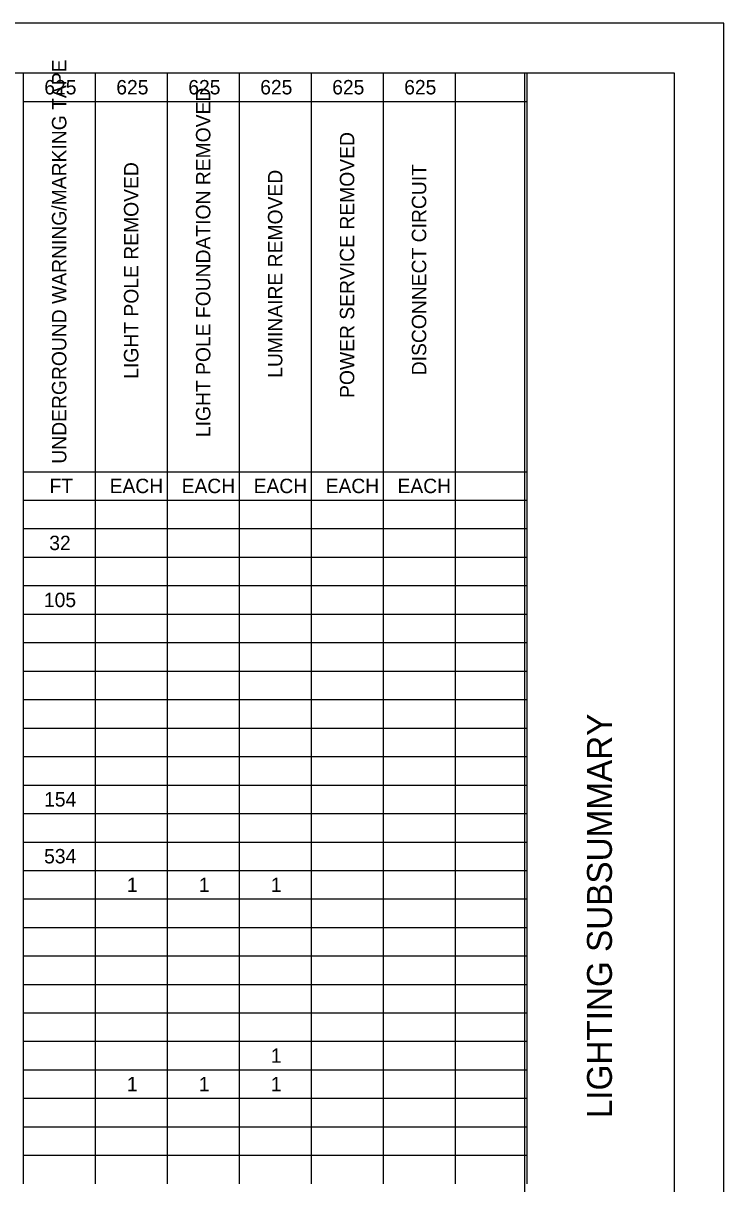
# Model space of a CAD drawing. Extents: x 0 to 34, y 0 to 22.
# Drawn here: x 26.95 to 34, y 10.33 to 22 of the extents above; entities that cross this region are included whole.
import ezdxf

# ---------------------------------------------------------------- set-up
doc = ezdxf.new("R2010")
doc.units = 0
for name, color, linetype in [('Default', 7, 'Continuous'), ('SH_Border', 7, 'Continuous'), ('SH_Cut_Line', 7, 'Continuous'), ('SH_Data', 7, 'Continuous')]:
    doc.layers.add(name, color=color, linetype=linetype)

msp = doc.modelspace()

# ---------------------------------------------------------------- linework, layer by layer
at = {"layer": 'Default'}
for p, q in [((26.955, 21.5), (27.679, 21.5)), ((26.955, 21.5), (26.955, 21.214)), ((27.679, 21.5), (29.85, 21.5)), ((27.679, 21.5), (27.679, 21.214)), ((28.402, 21.5), (28.402, 21.214)), ((29.126, 21.5), (29.126, 21.214)), ((29.85, 21.5), (30.574, 21.5)), ((29.85, 21.5), (29.85, 21.214)), ((30.574, 21.5), (31.297, 21.5)), ((30.574, 21.5), (30.574, 21.214)), ((31.297, 21.5), (32.021, 21.5)), ((31.297, 21.5), (31.297, 21.214)), ((32.021, 21.5), (32.021, 21.214)), ((26.955, 21.214), (27.679, 21.214)), ((26.955, 21.214), (26.955, 20.927)), ((27.679, 21.214), (29.85, 21.214)), ((27.679, 21.214), (27.679, 20.927)), ((28.402, 21.214), (28.402, 20.927)), ((29.126, 21.214), (29.126, 20.927)), ((29.85, 21.214), (30.574, 21.214)), ((29.85, 21.214), (29.85, 20.927)), ((30.574, 21.214), (31.297, 21.214)), ((30.574, 21.214), (30.574, 20.927)), ((31.297, 21.214), (32.021, 21.214)), ((31.297, 21.214), (31.297, 20.927)), ((32.021, 21.214), (32.021, 20.927)), ((26.955, 20.927), (26.955, 20.641)), ((27.679, 20.927), (27.679, 20.641)), ((28.402, 20.927), (28.402, 20.641)), ((29.126, 20.927), (29.126, 20.641)), ((29.85, 20.927), (29.85, 20.641)), ((30.574, 20.927), (30.574, 20.641)), ((31.297, 20.927), (31.297, 20.641)), ((32.021, 20.927), (32.021, 20.641)), ((26.955, 20.641), (26.955, 20.354)), ((27.679, 20.641), (27.679, 20.354)), ((28.402, 20.641), (28.402, 20.354)), ((29.126, 20.641), (29.126, 20.354)), ((29.85, 20.641), (29.85, 20.354)), ((30.574, 20.641), (30.574, 20.354)), ((31.297, 20.641), (31.297, 20.354)), ((32.021, 20.641), (32.021, 20.354)), ((26.955, 20.354), (26.955, 20.068)), ((27.679, 20.354), (27.679, 20.068)), ((28.402, 20.354), (28.402, 20.068)), ((29.126, 20.354), (29.126, 20.068)), ((29.85, 20.354), (29.85, 20.068)), ((30.574, 20.354), (30.574, 20.068)), ((31.297, 20.354), (31.297, 20.068)), ((32.021, 20.354), (32.021, 20.068)), ((26.955, 20.068), (26.955, 19.782)), ((27.679, 20.068), (27.679, 19.782)), ((28.402, 20.068), (28.402, 19.782)), ((29.126, 20.068), (29.126, 19.782)), ((29.85, 20.068), (29.85, 19.782)), ((30.574, 20.068), (30.574, 19.782)), ((31.297, 20.068), (31.297, 19.782)), ((32.021, 20.068), (32.021, 19.782)), ((26.955, 19.782), (26.955, 19.495)), ((27.679, 19.782), (27.679, 19.495)), ((28.402, 19.782), (28.402, 19.495)), ((29.126, 19.782), (29.126, 19.495)), ((29.85, 19.782), (29.85, 19.495)), ((30.574, 19.782), (30.574, 19.495)), ((31.297, 19.782), (31.297, 19.495)), ((32.021, 19.782), (32.021, 19.495)), ((26.955, 19.495), (26.955, 19.209)), ((27.679, 19.495), (27.679, 19.209)), ((28.402, 19.495), (28.402, 19.209)), ((29.126, 19.495), (29.126, 19.209)), ((29.85, 19.495), (29.85, 19.209)), ((30.574, 19.495), (30.574, 19.209)), ((31.297, 19.495), (31.297, 19.209)), ((32.021, 19.495), (32.021, 19.209)), ((26.955, 19.209), (26.955, 18.922)), ((27.679, 19.209), (27.679, 18.922)), ((28.402, 19.209), (28.402, 18.922)), ((29.126, 19.209), (29.126, 18.922)), ((29.85, 19.209), (29.85, 18.922)), ((30.574, 19.209), (30.574, 18.922)), ((31.297, 19.209), (31.297, 18.922)), ((32.021, 19.209), (32.021, 18.922)), ((26.955, 18.922), (26.955, 18.636)), ((27.679, 18.922), (27.679, 18.636)), ((28.402, 18.922), (28.402, 18.636)), ((29.126, 18.922), (29.126, 18.636)), ((29.85, 18.922), (29.85, 18.636)), ((30.574, 18.922), (30.574, 18.636)), ((31.297, 18.922), (31.297, 18.636)), ((32.021, 18.922), (32.021, 18.636)), ((26.955, 18.636), (26.955, 18.35)), ((27.679, 18.636), (27.679, 18.35)), ((28.402, 18.636), (28.402, 18.35)), ((29.126, 18.636), (29.126, 18.35)), ((29.85, 18.636), (29.85, 18.35)), ((30.574, 18.636), (30.574, 18.35)), ((31.297, 18.636), (31.297, 18.35)), ((32.021, 18.636), (32.021, 18.35)), ((26.955, 18.35), (26.955, 18.063)), ((27.679, 18.35), (27.679, 18.063)), ((28.402, 18.35), (28.402, 18.063)), ((29.126, 18.35), (29.126, 18.063)), ((29.85, 18.35), (29.85, 18.063)), ((30.574, 18.35), (30.574, 18.063)), ((31.297, 18.35), (31.297, 18.063)), ((32.021, 18.35), (32.021, 18.063)), ((26.955, 18.063), (26.955, 17.777)), ((27.679, 18.063), (27.679, 17.777)), ((28.402, 18.063), (28.402, 17.777)), ((29.126, 18.063), (29.126, 17.777)), ((29.85, 18.063), (29.85, 17.777)), ((30.574, 18.063), (30.574, 17.777)), ((31.297, 18.063), (31.297, 17.777)), ((32.021, 18.063), (32.021, 17.777)), ((26.955, 17.777), (26.955, 17.49)), ((27.679, 17.777), (27.679, 17.49)), ((28.402, 17.777), (28.402, 17.49)), ((29.126, 17.777), (29.126, 17.49)), ((29.85, 17.777), (29.85, 17.49)), ((30.574, 17.777), (30.574, 17.49)), ((31.297, 17.777), (31.297, 17.49)), ((32.021, 17.777), (32.021, 17.49)), ((26.955, 17.49), (27.679, 17.49)), ((26.955, 17.49), (26.955, 17.204)), ((27.679, 17.49), (29.85, 17.49)), ((27.679, 17.49), (27.679, 17.204)), ((28.402, 17.49), (28.402, 17.204)), ((29.126, 17.49), (29.126, 17.204)), ((29.85, 17.49), (30.574, 17.49)), ((29.85, 17.49), (29.85, 17.204)), ((30.574, 17.49), (31.297, 17.49)), ((30.574, 17.49), (30.574, 17.204)), ((31.297, 17.49), (32.021, 17.49)), ((31.297, 17.49), (31.297, 17.204)), ((32.021, 17.49), (32.021, 17.204)), ((26.955, 17.204), (27.679, 17.204)), ((26.955, 17.204), (26.955, 16.918)), ((27.679, 17.204), (29.85, 17.204)), ((27.679, 17.204), (27.679, 16.918)), ((28.402, 17.204), (28.402, 16.918)), ((29.126, 17.204), (29.126, 16.918)), ((29.85, 17.204), (30.574, 17.204)), ((29.85, 17.204), (29.85, 16.918)), ((30.574, 17.204), (31.297, 17.204)), ((30.574, 17.204), (30.574, 16.918)), ((31.297, 17.204), (32.021, 17.204)), ((31.297, 17.204), (31.297, 16.918)), ((32.021, 17.204), (32.021, 16.918)), ((26.955, 16.918), (27.679, 16.918)), ((26.955, 16.918), (26.955, 16.631)), ((27.679, 16.918), (29.85, 16.918)), ((27.679, 16.918), (27.679, 16.631)), ((28.402, 16.918), (28.402, 16.631)), ((29.126, 16.918), (29.126, 16.631)), ((29.85, 16.918), (30.574, 16.918)), ((29.85, 16.918), (29.85, 16.631)), ((30.574, 16.918), (31.297, 16.918)), ((30.574, 16.918), (30.574, 16.631)), ((31.297, 16.918), (32.021, 16.918)), ((31.297, 16.918), (31.297, 16.631)), ((32.021, 16.918), (32.021, 16.631)), ((26.955, 16.631), (27.679, 16.631)), ((26.955, 16.631), (26.955, 16.345)), ((27.679, 16.631), (29.85, 16.631)), ((27.679, 16.631), (27.679, 16.345)), ((28.402, 16.631), (28.402, 16.345)), ((29.126, 16.631), (29.126, 16.345)), ((29.85, 16.631), (30.574, 16.631)), ((29.85, 16.631), (29.85, 16.345)), ((30.574, 16.631), (31.297, 16.631)), ((30.574, 16.631), (30.574, 16.345)), ((31.297, 16.631), (32.021, 16.631)), ((31.297, 16.631), (31.297, 16.345)), ((32.021, 16.631), (32.021, 16.345)), ((26.955, 16.345), (27.679, 16.345)), ((26.955, 16.345), (26.955, 16.058)), ((27.679, 16.345), (29.85, 16.345)), ((27.679, 16.345), (27.679, 16.058)), ((28.402, 16.345), (28.402, 16.058)), ((29.126, 16.345), (29.126, 16.058)), ((29.85, 16.345), (30.574, 16.345)), ((29.85, 16.345), (29.85, 16.058)), ((30.574, 16.345), (31.297, 16.345)), ((30.574, 16.345), (30.574, 16.058)), ((31.297, 16.345), (32.021, 16.345)), ((31.297, 16.345), (31.297, 16.058)), ((32.021, 16.345), (32.021, 16.058)), ((26.955, 16.058), (27.679, 16.058)), ((26.955, 16.058), (26.955, 15.772)), ((27.679, 16.058), (29.85, 16.058)), ((27.679, 16.058), (27.679, 15.772)), ((28.402, 16.058), (28.402, 15.772)), ((29.126, 16.058), (29.126, 15.772)), ((29.85, 16.058), (30.574, 16.058)), ((29.85, 16.058), (29.85, 15.772)), ((30.574, 16.058), (31.297, 16.058)), ((30.574, 16.058), (30.574, 15.772)), ((31.297, 16.058), (32.021, 16.058)), ((31.297, 16.058), (31.297, 15.772)), ((32.021, 16.058), (32.021, 15.772)), ((26.955, 15.772), (27.679, 15.772)), ((26.955, 15.772), (26.955, 15.486)), ((27.679, 15.772), (29.85, 15.772)), ((27.679, 15.772), (27.679, 15.486)), ((28.402, 15.772), (28.402, 15.486)), ((29.126, 15.772), (29.126, 15.486)), ((29.85, 15.772), (30.574, 15.772)), ((29.85, 15.772), (29.85, 15.486)), ((30.574, 15.772), (31.297, 15.772)), ((30.574, 15.772), (30.574, 15.486)), ((31.297, 15.772), (32.021, 15.772)), ((31.297, 15.772), (31.297, 15.486)), ((32.021, 15.772), (32.021, 15.486)), ((26.955, 15.486), (27.679, 15.486)), ((26.955, 15.486), (26.955, 15.199)), ((27.679, 15.486), (29.85, 15.486)), ((27.679, 15.486), (27.679, 15.199)), ((28.402, 15.486), (28.402, 15.199)), ((29.126, 15.486), (29.126, 15.199)), ((29.85, 15.486), (30.574, 15.486)), ((29.85, 15.486), (29.85, 15.199)), ((30.574, 15.486), (31.297, 15.486)), ((30.574, 15.486), (30.574, 15.199)), ((31.297, 15.486), (32.021, 15.486)), ((31.297, 15.486), (31.297, 15.199)), ((32.021, 15.486), (32.021, 15.199)), ((26.955, 15.199), (27.679, 15.199)), ((26.955, 15.199), (26.955, 14.913)), ((27.679, 15.199), (29.85, 15.199)), ((27.679, 15.199), (27.679, 14.913)), ((28.402, 15.199), (28.402, 14.913)), ((29.126, 15.199), (29.126, 14.913)), ((29.85, 15.199), (30.574, 15.199)), ((29.85, 15.199), (29.85, 14.913)), ((30.574, 15.199), (31.297, 15.199)), ((30.574, 15.199), (30.574, 14.913)), ((31.297, 15.199), (32.021, 15.199)), ((31.297, 15.199), (31.297, 14.913)), ((32.021, 15.199), (32.021, 14.913)), ((26.955, 14.913), (27.679, 14.913)), ((26.955, 14.913), (26.955, 14.626)), ((27.679, 14.913), (29.85, 14.913)), ((27.679, 14.913), (27.679, 14.626)), ((28.402, 14.913), (28.402, 14.626)), ((29.126, 14.913), (29.126, 14.626)), ((29.85, 14.913), (30.574, 14.913)), ((29.85, 14.913), (29.85, 14.626)), ((30.574, 14.913), (31.297, 14.913)), ((30.574, 14.913), (30.574, 14.626)), ((31.297, 14.913), (32.021, 14.913)), ((31.297, 14.913), (31.297, 14.626)), ((32.021, 14.913), (32.021, 14.626)), ((26.955, 14.626), (27.679, 14.626)), ((26.955, 14.626), (26.955, 14.34)), ((27.679, 14.626), (29.85, 14.626)), ((27.679, 14.626), (27.679, 14.34)), ((28.402, 14.626), (28.402, 14.34)), ((29.126, 14.626), (29.126, 14.34)), ((29.85, 14.626), (30.574, 14.626)), ((29.85, 14.626), (29.85, 14.34)), ((30.574, 14.626), (31.297, 14.626)), ((30.574, 14.626), (30.574, 14.34)), ((31.297, 14.626), (32.021, 14.626)), ((31.297, 14.626), (31.297, 14.34)), ((32.021, 14.626), (32.021, 14.34)), ((26.955, 14.34), (27.679, 14.34)), ((26.955, 14.34), (26.955, 14.054)), ((27.679, 14.34), (29.85, 14.34)), ((27.679, 14.34), (27.679, 14.054)), ((28.402, 14.34), (28.402, 14.054)), ((29.126, 14.34), (29.126, 14.054)), ((29.85, 14.34), (30.574, 14.34)), ((29.85, 14.34), (29.85, 14.054)), ((30.574, 14.34), (31.297, 14.34)), ((30.574, 14.34), (30.574, 14.054)), ((31.297, 14.34), (32.021, 14.34)), ((31.297, 14.34), (31.297, 14.054)), ((32.021, 14.34), (32.021, 14.054)), ((26.955, 14.054), (27.679, 14.054)), ((26.955, 14.054), (26.955, 13.767)), ((27.679, 14.054), (29.85, 14.054)), ((27.679, 14.054), (27.679, 13.767)), ((28.402, 14.054), (28.402, 13.767)), ((29.126, 14.054), (29.126, 13.767)), ((29.85, 14.054), (30.574, 14.054)), ((29.85, 14.054), (29.85, 13.767)), ((30.574, 14.054), (31.297, 14.054)), ((30.574, 14.054), (30.574, 13.767)), ((31.297, 14.054), (32.021, 14.054)), ((31.297, 14.054), (31.297, 13.767)), ((32.021, 14.054), (32.021, 13.767)), ((26.955, 13.767), (27.679, 13.767)), ((26.955, 13.767), (26.955, 13.481)), ((27.679, 13.767), (29.85, 13.767)), ((27.679, 13.767), (27.679, 13.481)), ((28.402, 13.767), (28.402, 13.481)), ((29.126, 13.767), (29.126, 13.481)), ((29.85, 13.767), (30.574, 13.767)), ((29.85, 13.767), (29.85, 13.481)), ((30.574, 13.767), (31.297, 13.767)), ((30.574, 13.767), (30.574, 13.481)), ((31.297, 13.767), (32.021, 13.767)), ((31.297, 13.767), (31.297, 13.481)), ((32.021, 13.767), (32.021, 13.481)), ((26.955, 13.481), (27.679, 13.481)), ((26.955, 13.481), (26.955, 13.195)), ((27.679, 13.481), (29.85, 13.481)), ((27.679, 13.481), (27.679, 13.195)), ((28.402, 13.481), (28.402, 13.195)), ((29.126, 13.481), (29.126, 13.195)), ((29.85, 13.481), (30.574, 13.481)), ((29.85, 13.481), (29.85, 13.195)), ((30.574, 13.481), (31.297, 13.481)), ((30.574, 13.481), (30.574, 13.195)), ((31.297, 13.481), (32.021, 13.481)), ((31.297, 13.481), (31.297, 13.195)), ((32.021, 13.481), (32.021, 13.195)), ((26.955, 13.195), (27.679, 13.195)), ((26.955, 13.195), (26.955, 12.908)), ((27.679, 13.195), (29.85, 13.195)), ((27.679, 13.195), (27.679, 12.908)), ((28.402, 13.195), (28.402, 12.908)), ((29.126, 13.195), (29.126, 12.908)), ((29.85, 13.195), (30.574, 13.195)), ((29.85, 13.195), (29.85, 12.908)), ((30.574, 13.195), (31.297, 13.195)), ((30.574, 13.195), (30.574, 12.908)), ((31.297, 13.195), (32.021, 13.195)), ((31.297, 13.195), (31.297, 12.908)), ((32.021, 13.195), (32.021, 12.908)), ((26.955, 12.908), (27.679, 12.908)), ((26.955, 12.908), (26.955, 12.622)), ((27.679, 12.908), (29.85, 12.908)), ((27.679, 12.908), (27.679, 12.622)), ((28.402, 12.908), (28.402, 12.622)), ((29.126, 12.908), (29.126, 12.622)), ((29.85, 12.908), (30.574, 12.908)), ((29.85, 12.908), (29.85, 12.622)), ((30.574, 12.908), (31.297, 12.908)), ((30.574, 12.908), (30.574, 12.622)), ((31.297, 12.908), (32.021, 12.908)), ((31.297, 12.908), (31.297, 12.622)), ((32.021, 12.908), (32.021, 12.622)), ((26.955, 12.622), (27.679, 12.622)), ((26.955, 12.622), (26.955, 12.335)), ((27.679, 12.622), (29.85, 12.622)), ((27.679, 12.622), (27.679, 12.335)), ((28.402, 12.622), (28.402, 12.335)), ((29.126, 12.622), (29.126, 12.335)), ((29.85, 12.622), (30.574, 12.622)), ((29.85, 12.622), (29.85, 12.335)), ((30.574, 12.622), (31.297, 12.622)), ((30.574, 12.622), (30.574, 12.335)), ((31.297, 12.622), (32.021, 12.622)), ((31.297, 12.622), (31.297, 12.335)), ((32.021, 12.622), (32.021, 12.335)), ((26.955, 12.335), (27.679, 12.335)), ((26.955, 12.335), (26.955, 12.049)), ((27.679, 12.335), (29.85, 12.335)), ((27.679, 12.335), (27.679, 12.049)), ((28.402, 12.335), (28.402, 12.049)), ((29.126, 12.335), (29.126, 12.049)), ((29.85, 12.335), (30.574, 12.335)), ((29.85, 12.335), (29.85, 12.049)), ((30.574, 12.335), (31.297, 12.335)), ((30.574, 12.335), (30.574, 12.049)), ((31.297, 12.335), (32.021, 12.335)), ((31.297, 12.335), (31.297, 12.049)), ((32.021, 12.335), (32.021, 12.049)), ((26.955, 12.049), (27.679, 12.049)), ((26.955, 12.049), (26.955, 11.763)), ((27.679, 12.049), (29.85, 12.049)), ((27.679, 12.049), (27.679, 11.763)), ((28.402, 12.049), (28.402, 11.763)), ((29.126, 12.049), (29.126, 11.763)), ((29.85, 12.049), (30.574, 12.049)), ((29.85, 12.049), (29.85, 11.763)), ((30.574, 12.049), (31.297, 12.049)), ((30.574, 12.049), (30.574, 11.763)), ((31.297, 12.049), (32.021, 12.049)), ((31.297, 12.049), (31.297, 11.763)), ((32.021, 12.049), (32.021, 11.763)), ((26.955, 11.763), (27.679, 11.763)), ((26.955, 11.763), (26.955, 11.476)), ((27.679, 11.763), (29.85, 11.763)), ((27.679, 11.763), (27.679, 11.476)), ((28.402, 11.763), (28.402, 11.476)), ((29.126, 11.763), (29.126, 11.476)), ((29.85, 11.763), (30.574, 11.763)), ((29.85, 11.763), (29.85, 11.476)), ((30.574, 11.763), (31.297, 11.763)), ((30.574, 11.763), (30.574, 11.476)), ((31.297, 11.763), (32.021, 11.763)), ((31.297, 11.763), (31.297, 11.476)), ((32.021, 11.763), (32.021, 11.476)), ((26.955, 11.476), (27.679, 11.476)), ((26.955, 11.476), (26.955, 11.19)), ((27.679, 11.476), (29.85, 11.476)), ((27.679, 11.476), (27.679, 11.19)), ((28.402, 11.476), (28.402, 11.19)), ((29.126, 11.476), (29.126, 11.19)), ((29.85, 11.476), (30.574, 11.476)), ((29.85, 11.476), (29.85, 11.19)), ((30.574, 11.476), (31.297, 11.476)), ((30.574, 11.476), (30.574, 11.19)), ((31.297, 11.476), (32.021, 11.476)), ((31.297, 11.476), (31.297, 11.19)), ((32.021, 11.476), (32.021, 11.19)), ((26.955, 11.19), (27.679, 11.19)), ((26.955, 11.19), (26.955, 10.903)), ((27.679, 11.19), (29.85, 11.19)), ((27.679, 11.19), (27.679, 10.903)), ((28.402, 11.19), (28.402, 10.903)), ((29.126, 11.19), (29.126, 10.903)), ((29.85, 11.19), (30.574, 11.19)), ((29.85, 11.19), (29.85, 10.903)), ((30.574, 11.19), (31.297, 11.19)), ((30.574, 11.19), (30.574, 10.903)), ((31.297, 11.19), (32.021, 11.19)), ((31.297, 11.19), (31.297, 10.903)), ((32.021, 11.19), (32.021, 10.903)), ((26.955, 10.903), (27.679, 10.903)), ((26.955, 10.903), (26.955, 10.617)), ((27.679, 10.903), (29.85, 10.903)), ((27.679, 10.903), (27.679, 10.617)), ((28.402, 10.903), (28.402, 10.617)), ((29.126, 10.903), (29.126, 10.617)), ((29.85, 10.903), (30.574, 10.903)), ((29.85, 10.903), (29.85, 10.617)), ((30.574, 10.903), (31.297, 10.903)), ((30.574, 10.903), (30.574, 10.617)), ((31.297, 10.903), (32.021, 10.903)), ((31.297, 10.903), (31.297, 10.617)), ((32.021, 10.903), (32.021, 10.617)), ((26.955, 10.617), (27.679, 10.617)), ((26.955, 10.617), (26.955, 10.331)), ((27.679, 10.617), (29.85, 10.617)), ((27.679, 10.617), (27.679, 10.331)), ((28.402, 10.617), (28.402, 10.331)), ((29.126, 10.617), (29.126, 10.331)), ((29.85, 10.617), (30.574, 10.617)), ((29.85, 10.617), (29.85, 10.331)), ((30.574, 10.617), (31.297, 10.617)), ((30.574, 10.617), (30.574, 10.331)), ((31.297, 10.617), (32.021, 10.617)), ((31.297, 10.617), (31.297, 10.331)), ((32.021, 10.617), (32.021, 10.331))]:
    msp.add_line(p, q, dxfattribs=at)
at = {"layer": 'SH_Border'}
msp.add_line((32, 0.5), (32, 21.5), dxfattribs=at)
msp.add_lwpolyline([(1.5, 21.5), (33.5, 21.5), (33.5, 0.5), (1.5, 0.5)], close=True, dxfattribs=at)
at = {"layer": 'SH_Cut_Line'}
msp.add_lwpolyline([(0, 0), (34, 0), (34, 22), (0, 22)], close=True, dxfattribs=at)

# ---------------------------------------------------------------- texts
at = {"layer": 'Default'}
for s, p in [('UNDERGROUND WARNING/MARKING TAPE', (27.389, 17.571)), ('LIGHT POLE FOUNDATION REMOVED', (28.837, 17.838)), ('POWER SERVICE REMOVED', (30.284, 18.232)), ('LIGHT POLE REMOVED', (28.113, 18.425)), ('DISCONNECT CIRCUIT', (31.008, 18.46)), ('LUMINAIRE REMOVED', (29.561, 18.435))]:
    msp.add_text(s, height=0.14509, rotation=90, dxfattribs=at).set_placement(p)
for s, height, p in [('625', 0.1449, (27.167, 21.284)), ('625', 0.1449, (27.891, 21.284)), ('625', 0.1449, (28.615, 21.284)), ('625', 0.1449, (29.338, 21.284)), ('625', 0.1449, (30.062, 21.284)), ('625', 0.1449, (30.786, 21.284)), ('FT', 0.1449, (27.22, 17.275)), ('EACH', 0.1449, (27.824, 17.275)), ('EACH', 0.1449, (28.548, 17.275)), ('EACH', 0.1449, (29.272, 17.275)), ('EACH', 0.1449, (29.996, 17.275)), ('EACH', 0.1449, (30.719, 17.275)), ('32', 0.1449, (27.217, 16.702)), ('105', 0.1449, (27.163, 16.129)), ('154', 0.1449, (27.165, 14.124)), ('534', 0.1449, (27.165, 13.552)), ('1', 0.145, (27.998, 13.265)), ('1', 0.145, (28.722, 13.265)), ('1', 0.145, (29.446, 13.265)), ('1', 0.145, (29.446, 11.547)), ('1', 0.145, (27.998, 11.261)), ('1', 0.145, (28.722, 11.261)), ('1', 0.145, (29.446, 11.261))]:
    msp.add_text(s, height=height, dxfattribs=at).set_placement(p)
at = {"layer": 'SH_Data'}
msp.add_text('LIGHTING SUBSUMMARY', height=0.25, rotation=90, dxfattribs=at).set_placement((32.875, 10.99))

doc.saveas('drawing.dxf')
